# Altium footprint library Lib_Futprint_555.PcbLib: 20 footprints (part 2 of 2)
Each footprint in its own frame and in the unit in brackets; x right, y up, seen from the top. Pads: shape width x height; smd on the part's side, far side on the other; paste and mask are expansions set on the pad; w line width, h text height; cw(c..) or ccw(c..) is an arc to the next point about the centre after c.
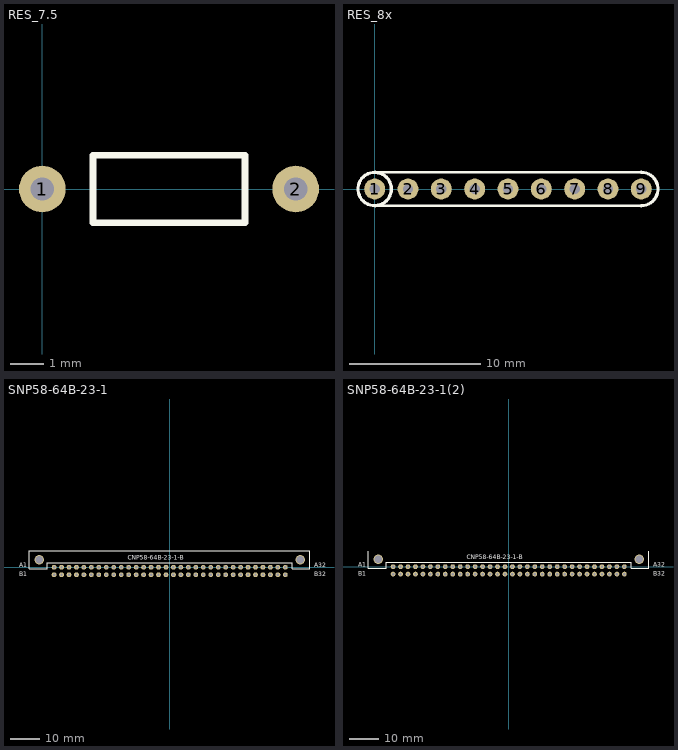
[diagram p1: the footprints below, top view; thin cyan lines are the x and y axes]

## RES_7.5 [mm]
pads (2):
  round 1.4 hole 0.7: 1(0,0) 2(7.62,0)
Top Overlay:
  lines w0.2: 1.524,-1.016 6.096,-1.016 6.096,1.016 1.524,1.016 1.524,-1.016
  text ".Designator" at 2.032,1.524 h1.52

## RES_8x [mm]
pads (9):
  round 1.6 hole 0.8: 1(0,0) 2(2.54,0) 3(5.08,0) 4(7.62,0) 5(10.16,0) 6(12.7,0) 7(15.24,0) 8(17.78,0) 9(20.32,0)
Top Overlay:
  circle w0.254: c0,0 r1.27
  lines w0.2: 0,-1.27 20.32,-1.27 ; 0,1.27 20.32,1.27
  lines w0.254: 20.32,-1.27 ccw(c20.32,0) 20.32,1.27

## SNP58-64B-23-1 [mm]
pads (64):
  round 1.6 hole 0.8: À1(-38.75,0) À2(-36.25,0) À3(-33.75,0) À4(-31.25,0) À5(-28.75,0) À6(-26.25,0) À7(-23.75,0) À8(-21.25,0) À9(-18.75,0) À10(-16.25,0) À11(-13.75,0) À12(-11.25,0) À13(-8.75,0) À14(-6.25,0) À15(-3.75,0) À16(-1.25,0) À17(1.25,0) À18(3.75,0) À19(6.25,0) À20(8.75,0) À21(11.25,0) À22(13.75,0) À23(16.25,0) À24(18.75,0) À25(21.25,0) À26(23.75,0) À27(26.25,0) À28(28.75,0) À29(31.25,0) À30(33.75,0) À31(36.25,0) À32(38.75,0) Á1(-38.75,-2.5) Á2(-36.25,-2.5) Á3(-33.75,-2.5) Á4(-31.25,-2.5) Á5(-28.75,-2.5) Á6(-26.25,-2.5) Á7(-23.75,-2.5) Á8(-21.25,-2.5) Á9(-18.75,-2.5) Á10(-16.25,-2.5) Á11(-13.75,-2.5) Á12(-11.25,-2.5) Á13(-8.75,-2.5) Á14(-6.25,-2.5) Á15(-3.75,-2.5) Á16(-1.25,-2.5) Á17(1.25,-2.5) Á18(3.75,-2.5) Á19(6.25,-2.5) Á20(8.75,-2.5) Á21(11.25,-2.5) Á22(13.75,-2.5) Á23(16.25,-2.5) Á24(18.75,-2.5) Á25(21.25,-2.5) Á26(23.75,-2.5) Á27(26.25,-2.5) Á28(28.75,-2.5) Á29(31.25,-2.5) Á30(33.75,-2.5) Á31(36.25,-2.5) Á32(38.75,-2.5)
via -43.75,2.5 diameter 3.2 hole 2.6
via 43.75,2.5 diameter 3.2 hole 2.6
Top Overlay:
  lines w0.2: -47,-0.5 -41,-0.5 -41,1.5 41,1.5 41,-0.5 47,-0.5 47,5.5 -47,5.5 -47,-0.5
  text "A32" at 48.5,0 h1.52
  text "B32" at 48.5,-3 h1.52
  text "B1" at -50.5,-3 h1.52
  text "A1" at -50.5,0 h1.52
  text "CNP58-64B-23-1-B" at -14,2.5 h1.52

## SNP58-64B-23-1(2) [mm]
pads (64):
  round 1.6 hole 0.8: À1(-38.75,0) À2(-36.25,0) À3(-33.75,0) À4(-31.25,0) À5(-28.75,0) À6(-26.25,0) À7(-23.75,0) À8(-21.25,0) À9(-18.75,0) À10(-16.25,0) À11(-13.75,0) À12(-11.25,0) À13(-8.75,0) À14(-6.25,0) À15(-3.75,0) À16(-1.25,0) À17(1.25,0) À18(3.75,0) À19(6.25,0) À20(8.75,0) À21(11.25,0) À22(13.75,0) À23(16.25,0) À24(18.75,0) À25(21.25,0) À26(23.75,0) À27(26.25,0) À28(28.75,0) À29(31.25,0) À30(33.75,0) À31(36.25,0) À32(38.75,0) Á1(-38.75,-2.5) Á2(-36.25,-2.5) Á3(-33.75,-2.5) Á4(-31.25,-2.5) Á5(-28.75,-2.5) Á6(-26.25,-2.5) Á7(-23.75,-2.5) Á8(-21.25,-2.5) Á9(-18.75,-2.5) Á10(-16.25,-2.5) Á11(-13.75,-2.5) Á12(-11.25,-2.5) Á13(-8.75,-2.5) Á14(-6.25,-2.5) Á15(-3.75,-2.5) Á16(-1.25,-2.5) Á17(1.25,-2.5) Á18(3.75,-2.5) Á19(6.25,-2.5) Á20(8.75,-2.5) Á21(11.25,-2.5) Á22(13.75,-2.5) Á23(16.25,-2.5) Á24(18.75,-2.5) Á25(21.25,-2.5) Á26(23.75,-2.5) Á27(26.25,-2.5) Á28(28.75,-2.5) Á29(31.25,-2.5) Á30(33.75,-2.5) Á31(36.25,-2.5) Á32(38.75,-2.5)
via 43.75,2.5 diameter 3.2 hole 2.6
via -43.75,2.5 diameter 3.2 hole 2.6
Top Overlay:
  lines w0.2: -47,5.08 -47,-0.5 -41,-0.5 -41,1.5 41,1.5 41,-0.5 47,-0.5 47,5.08
  text "CNP58-64B-23-1-B" at -14,2.5 h1.52
  text "A1" at -50.5,0 h1.52
  text "B1" at -50.5,-3 h1.52
  text "B32" at 48.5,-3 h1.52
  text "A32" at 48.5,0 h1.52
